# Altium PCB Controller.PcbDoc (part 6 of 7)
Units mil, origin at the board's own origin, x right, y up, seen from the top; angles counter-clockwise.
Board outline 9000 x 8000 mil, 6 copper layers (Top Layer, Layer 1, Layer 2, Layer 3, Layer 4, Bottom Layer), stack 61.699 mil thick; 761 components, 454 nets, 2369 pads, 1133 vias.
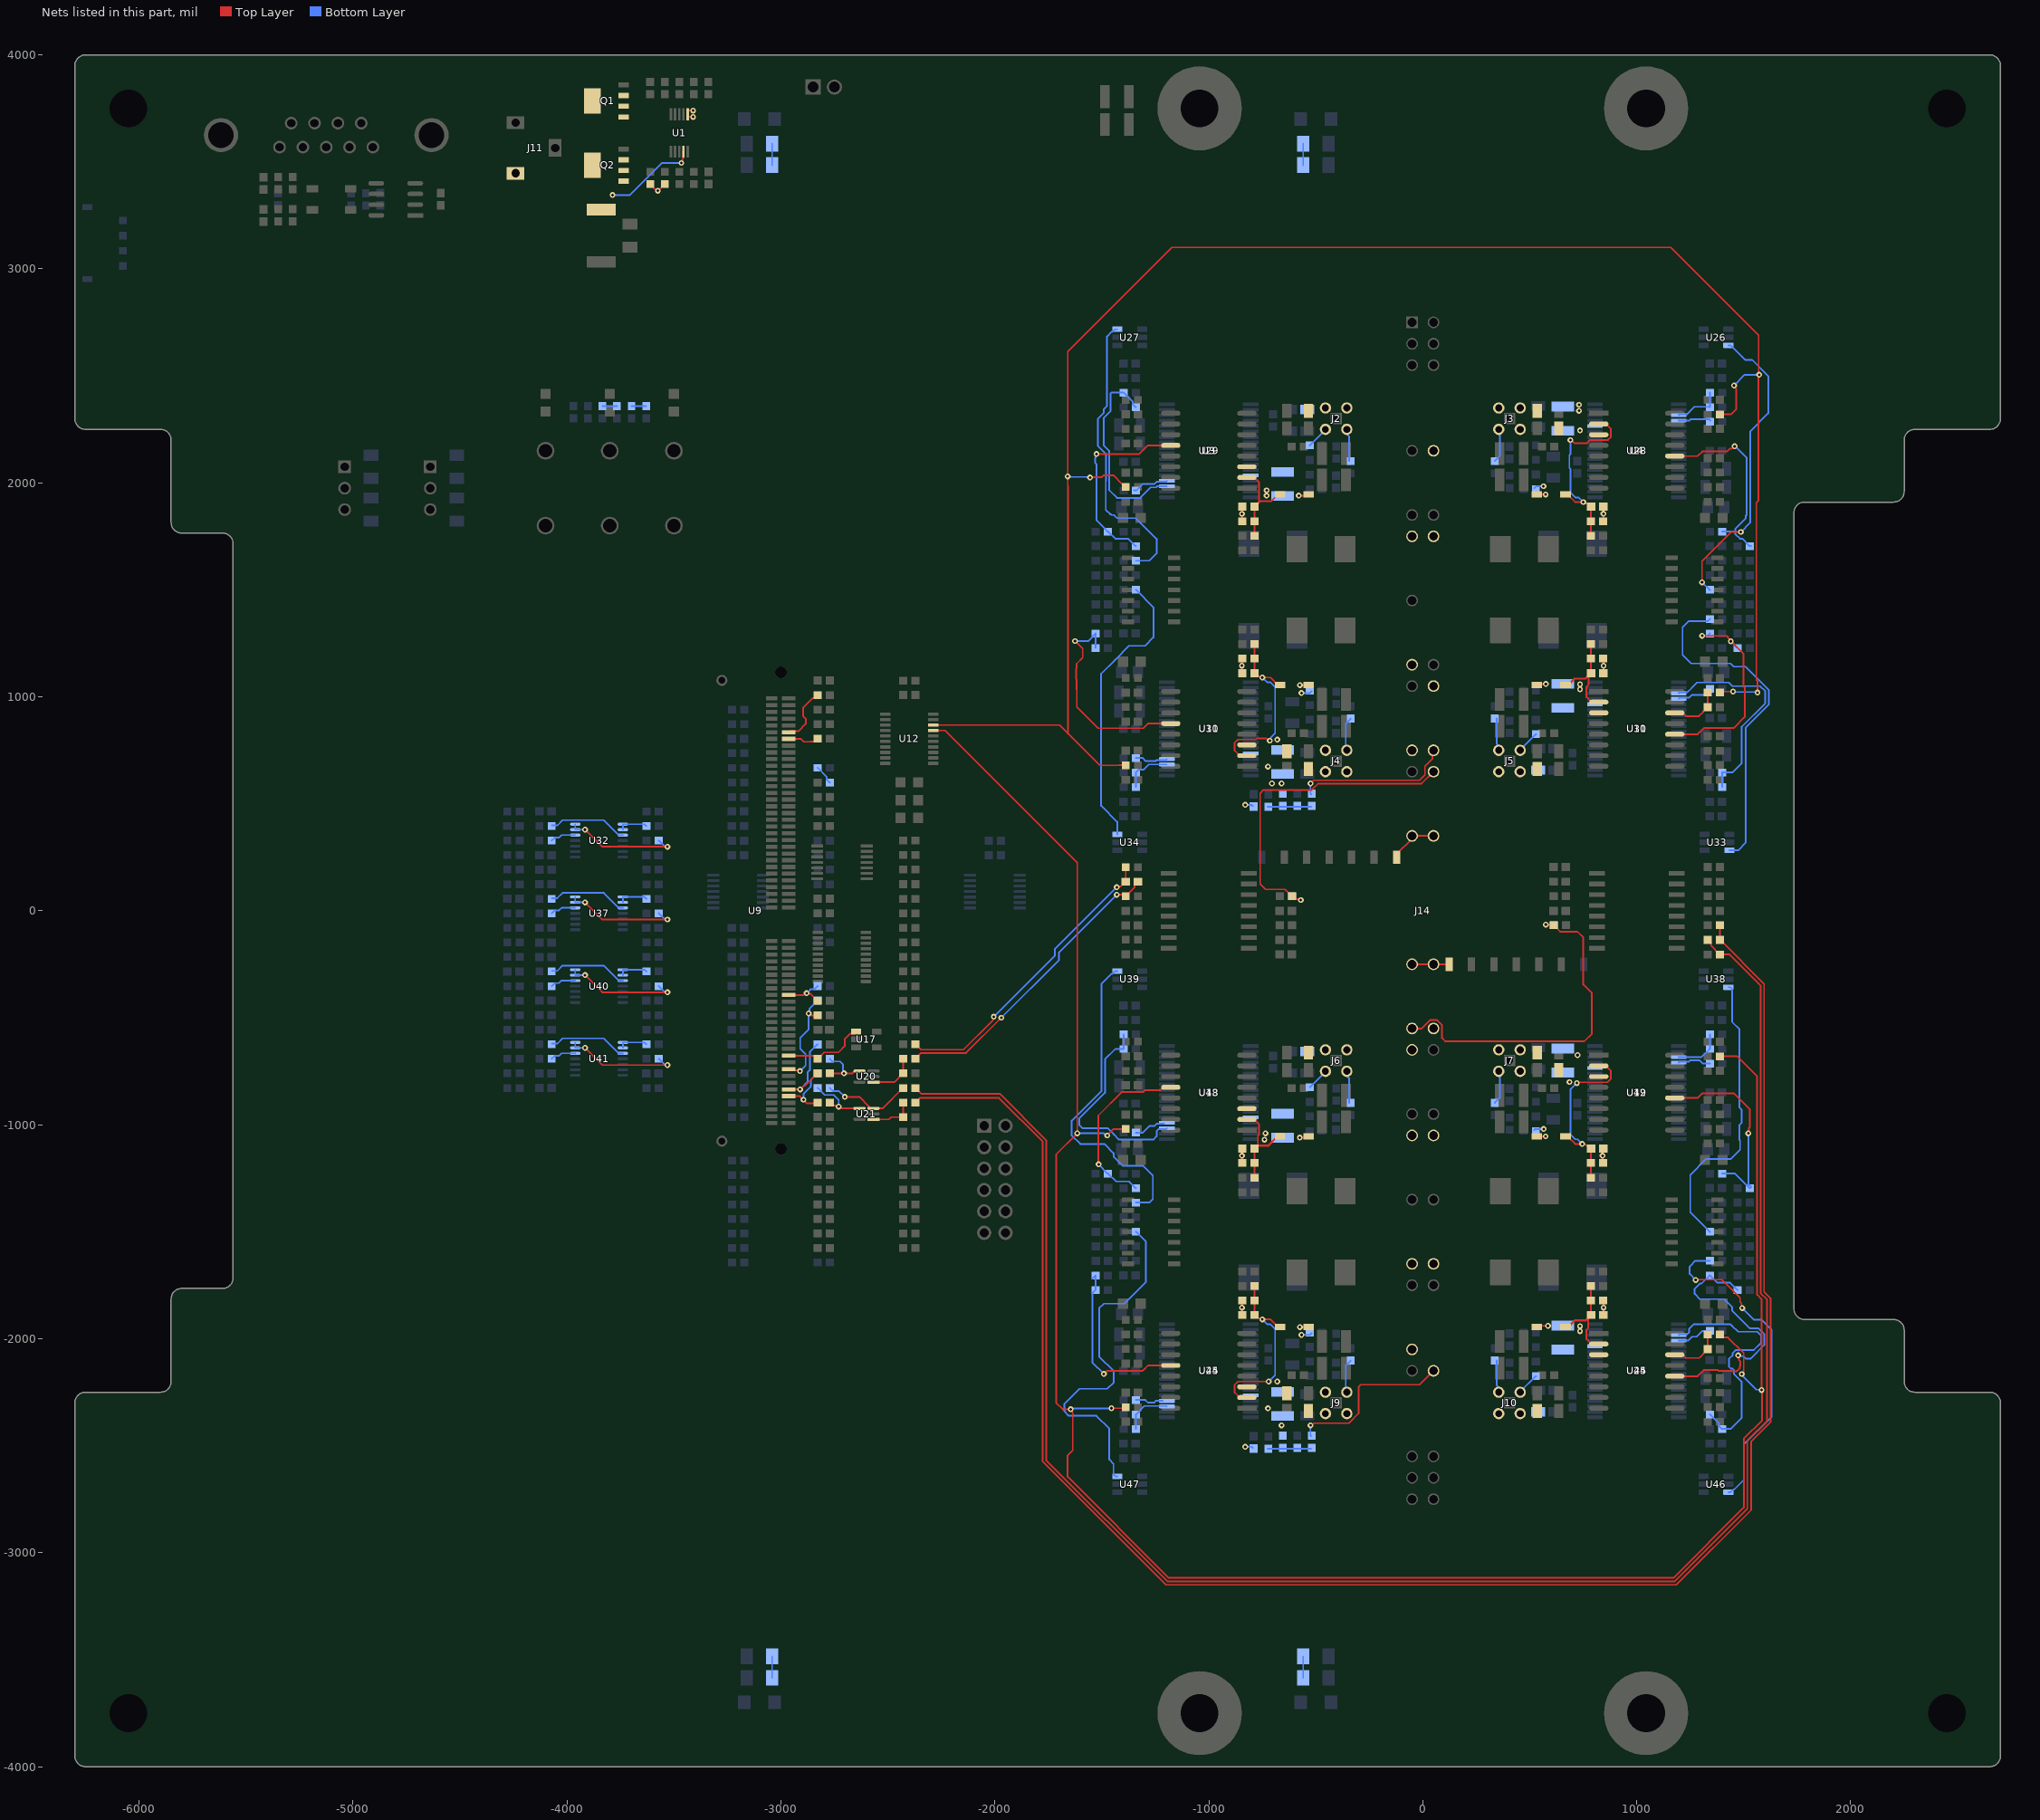
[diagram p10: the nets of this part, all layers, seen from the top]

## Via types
v1: diameter 27, hole 13, Top Layer to Bottom Layer, tented both sides, 1133 vias

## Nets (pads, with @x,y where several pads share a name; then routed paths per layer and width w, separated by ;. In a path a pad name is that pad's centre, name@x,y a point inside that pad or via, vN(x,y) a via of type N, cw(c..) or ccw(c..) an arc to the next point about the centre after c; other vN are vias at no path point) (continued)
NetR98_1: R98.1 R101.2 U20.1 | length 223.9
  Top Layer w8: U20.1@-2567.71,-800.59 -2470.12,-800.59 -2429.53,-760 R101.2@-2428.62,-760 R98.1@-2428.62,-692
NetR100_1: R100.1 R298.1 U20.4 | length 259.3
  Top Layer w8: R100.1@-2771.38,-760 v1(-2705,-760) -2666.14,-760 -2655.55,-749.41 U20.4@-2632.29,-749.41
  Bottom Layer w8: R298.1@-2771.38,-692 -2759.02,-704.36 -2724.24,-704.36 -2709.3,-719.3 -2709.3,-750.56 -2705,-754.86 v1(-2705,-760)
NetR102_1: R102.1 R308.2 U21.3 | length 427.1
  Top Layer w8: v1(-2701.19,-870) -2632.69,-870 -2589.93,-912.77 -2589.93,-920.27 -2586.79,-923.41 U21.3@-2567.71,-923.41 -2524.94,-923.41 -2429.53,-828 R102.1@-2428.62,-828
  Bottom Layer w8: R308.2@-2770.47,-828 R308.2@-2771.38,-828 -2757.42,-841.96 -2729.23,-841.96 v1(-2701.19,-870)
NetR107_1: R107.1 R308.1 U21.4 | length 296.4
  Top Layer w8: R107.1@-2771.38,-896 -2757.42,-909.96 v1@-2740.19,-909.96 ; v1(-2730,-915) -2724.86,-915 -2716.45,-923.41 U21.4@-2632.29,-923.41
  Bottom Layer w8: R308.1@-2828.62,-828 -2827.72,-828 -2794.76,-860.96 -2752.64,-860.96 -2730,-883.59 v1(-2730,-915) v1@-2733.64,-911.36
NetR108_1: R108.1 R112.2 U21.1 | length 212.1
  Top Layer w8: U21.1@-2568.14,-975 -2494.48,-975 -2484.07,-964.59 -2429.21,-964.59 R112.2@-2428.62,-964 R108.1@-2428.62,-896
NetR156_1: R156.1 R158.2 | length 100
  Bottom Layer w8: R158.2@-559.1,3485 R156.1@-559.1,3585
NetR157_1: R157.1 R159.2 | length 100
  Bottom Layer w8: R159.2@-3040.9,3485 R157.1@-3040.9,3585
NetR167_2: R167.2 R168.1 | length 68
  Bottom Layer w8: R168.1@-3698,2358.62 R167.2@-3630,2358.62
NetR169_1: R169.1 R170.2 | length 68
  Bottom Layer w8: R170.2@-3834,2358.62 R169.1@-3766,2358.62
NetR173_1: R173.1 U28.4 | length 155
  Bottom Layer w8: U28.4@1195.87,2290.75 1245.75,2290.75 1252.4,2297.4 1337.6,2297.4 R173.1@1345,2290
NetR185_1: R185.1 U29.4 | length 172.5
  Bottom Layer w8: R185.1@-1350,1965 -1338.47,1965 -1308.47,1995 -1253.96,1995 -1244.28,2004.67 -1200.44,2004.67 U29.4@-1195.87,2009.25
NetR211_1: R211.1 U30.4 | length 160.4
  Bottom Layer w8: U30.4@1195.87,990.75 1200.6,995.48 1244.28,995.48 1258.06,1009.26 1312.74,1009.26 1333.47,1030 R211.1@1340,1030
NetR228_1: R228.1 U31.4 | length 155.4
  Bottom Layer w8: R228.1@-1341.38,714 -1309,714 -1294.66,699.66 -1249.3,699.66 -1244.28,704.67 -1200.44,704.67 U31.4@-1195.87,709.25
NetR229_2: R229.2 R233.1 | length 92.8
  Bottom Layer w8: R229.2@-2828.62,668 -2827.72,668 -2786.24,626.52 -2786.24,613.96 -2772.28,600 R233.1@-2771.38,600
NetR244_1: R244.1 U32.8 U32.9 | length 139.4
  Bottom Layer w8: U32.9@-3738.78,379.18 U32.8@-3738.78,404.77 -3637.39,404.77 R244.1@-3628.62,396
NetR245_2: R245.2 U32.10 | length 371.8
  Bottom Layer w8: R245.2@-4071.38,399 -4045,399 -4020.34,423.66 -3827.69,423.66 -3757.62,353.59 U32.10@-3738.78,353.59
NetR246_1: R246.1 U32.6 U32.7 | length 543.4
  Top Layer w8: v1(-3915.18,379.18) -3835,299 v1(-3530,299)
  Bottom Layer w8: U32.7@-3961.22,404.77 U32.6@-3961.22,379.18 v1(-3915.18,379.18) ; R246.1@-3571.38,328 -3570.47,328 -3545.11,302.64 -3533.64,302.64 v1(-3530,299)
NetR247_2: R247.2 U32.5 | length 121.1
  Bottom Layer w8: R247.2@-4071.38,328 -4057.42,341.96 -4037.04,341.96 -4025,354 -3961.63,354 U32.5@-3961.22,353.59
NetR262_1: R262.1 U37.8 U37.9 | length 139.4
  Bottom Layer w8: U37.9@-3738.78,39.18 U37.8@-3738.78,64.77 -3637.39,64.77 R262.1@-3628.62,56
NetR263_2: R263.2 U37.10 | length 371.8
  Bottom Layer w8: R263.2@-4071.38,59 -4045,59 -4020.34,83.66 -3827.69,83.66 -3757.62,13.59 U37.10@-3738.78,13.59
NetR264_1: R264.1 U37.6 U37.7 | length 543.4
  Top Layer w8: v1(-3915.18,39.18) -3835,-41 v1(-3530,-41)
  Bottom Layer w8: U37.7@-3961.22,64.77 U37.6@-3961.22,39.18 v1(-3915.18,39.18) ; R264.1@-3571.38,-12 -3570.47,-12 -3545.11,-37.36 -3533.64,-37.36 v1(-3530,-41)
NetR265_2: R265.2 U37.5 | length 121.1
  Bottom Layer w8: R265.2@-4071.38,-12 -4057.42,1.96 -4037.04,1.96 -4025,14 -3961.63,14 U37.5@-3961.22,13.59
NetR277_1: R277.1 U40.8 U40.9 | length 139.4
  Bottom Layer w8: U40.9@-3738.78,-300.82 U40.8@-3738.78,-275.23 -3637.39,-275.23 R277.1@-3628.62,-284
NetR278_2: R278.2 U40.10 | length 371.8
  Bottom Layer w8: R278.2@-4071.38,-281 -4045,-281 -4020.34,-256.34 -3827.69,-256.34 -3757.62,-326.41 U40.10@-3738.78,-326.41
NetR279_1: R279.1 U40.6 U40.7 | length 543.4
  Top Layer w8: v1(-3915.18,-300.82) -3835,-381 v1(-3530,-381)
  Bottom Layer w8: U40.7@-3961.22,-275.23 U40.6@-3961.22,-300.82 v1(-3915.18,-300.82) ; R279.1@-3571.38,-352 -3570.47,-352 -3545.11,-377.36 -3533.64,-377.36 v1(-3530,-381)
NetR280_2: R280.2 U40.5 | length 121.1
  Bottom Layer w8: R280.2@-4071.38,-352 -4057.42,-338.04 -4037.04,-338.04 -4025,-326 -3961.63,-326 U40.5@-3961.22,-326.41
NetR293_1: R293.1 U41.8 U41.9 | length 139.4
  Bottom Layer w8: U41.9@-3738.78,-640.82 U41.8@-3738.78,-615.23 -3637.39,-615.23 R293.1@-3628.62,-624
NetR294_2: R294.2 U41.10 | length 371.8
  Bottom Layer w8: R294.2@-4071.38,-621 -4045,-621 -4020.34,-596.34 -3827.69,-596.34 -3757.62,-666.41 U41.10@-3738.78,-666.41
NetR300_1: R300.1 U41.6 U41.7 | length 543.4
  Top Layer w8: v1(-3915.18,-640.82) -3835,-721 v1(-3530,-721)
  Bottom Layer w8: U41.7@-3961.22,-615.23 U41.6@-3961.22,-640.82 v1(-3915.18,-640.82) ; R300.1@-3571.38,-692 -3570.47,-692 -3545.11,-717.36 -3533.64,-717.36 v1(-3530,-721)
NetR301_2: R301.2 U41.5 | length 121.1
  Bottom Layer w8: R301.2@-4071.38,-692 -4057.42,-678.04 -4037.04,-678.04 -4025,-666 -3961.63,-666 U41.5@-3961.22,-666.41
NetR303_1: R303.1 U42.4 | length 155.4
  Bottom Layer w8: U42.4@1195.87,-709.25 1200.44,-704.67 1244.28,-704.67 1249.3,-699.66 1294.66,-699.66 1309,-714 R303.1@1341.38,-714
NetR323_1: R323.1 U43.4 | length 148.8
  Bottom Layer w8: R323.1@-1341.38,-1037 -1307.85,-1037 -1275.85,-1005 -1253.8,-1005 -1244.28,-995.48 -1210.48,-995.48 U43.4@-1210,-995
NetR361_1: R361.1 U44.4 | length 162.5
  Bottom Layer w8: U44.4@1195.87,-2009.25 1239.69,-2009.25 1258.44,-1990.5 1280.35,-1990.5 1305.85,-1965 R361.1@1340,-1965
NetR373_1: R373.1 U45.4 | length 135.1
  Bottom Layer w8: R373.1@-1341.38,-2286 -1296.73,-2286 -1284.23,-2298.5 -1254.44,-2298.5 -1245.94,-2290 U45.4@-1215,-2290
NetR382_2: R382.2 R384.1 | length 100
  Bottom Layer w8: R384.1@-559.1,-3585 R382.2@-559.1,-3485
NetR383_2: R383.2 R385.1 | length 100
  Bottom Layer w8: R385.1@-3040.9,-3585 R383.2@-3040.9,-3485
NTC_P: J14.042 R237.1 | length 736.2
  Top Layer w8: v1(-525,595) -510,610 -15,610 10,635 10,675 45.64,710.64 45.64,745.64 J14.042@50,750
  Bottom Layer w8: v1(-525,595) -525,547.62 R237.1@-521,543.62
NTC_P_BIAS: R237.2 R238.1 R239.2 R240.2 | length 204
  Bottom Layer w8: R240.2@-725,486.38 -657,486.38 -589,486.38 R237.2@-521,486.38
NTC_S: J14.100 R378.1 | length 806.5
  Top Layer w8: v1(-525,-2405) -520.81,-2405 -510.81,-2395 -345.73,-2395 -300,-2349.27 -300,-2225 -290,-2215 -15,-2215 J14.100@50,-2150
  Bottom Layer w8: v1(-525,-2405) -525,-2452.38 R378.1@-521,-2456.38
NTC_S_BIAS: R378.2 R379.1 R380.2 R381.2 | length 204
  Bottom Layer w8: R381.2@-725,-2513.62 -657,-2513.62 -589,-2513.62 R378.2@-521,-2513.62
OC_1P: C22.1 D15.1 R37.1 R39.2 U11.2 | length 465
  Top Layer w8: D15.1@656.93,1055 D15.1@686.5,1055 ; C22.1@775,1099.58 775,1056.56 764.89,1046.46 764.89,998.46 788.35,975 U11.2@822.22,975 ; C22.1@786.42,1111 C22.1@786.42,1111 R39.2@786.38,1179 R37.1@786.38,1247
  Top Layer w10: D15.1@686.5,1055 686.5,1061.81 709.69,1085 760.42,1085 782.71,1107.29 C22.1@786.42,1111
OC_1S: C74.1 D30.1 R141.1 R143.2 U25.2 | length 463.7
  Top Layer w8: D30.1@656.93,-1945 D30.1@686.5,-1945 ; C74.1@772.97,-1901.5 772.97,-1950.49 764.89,-1958.57 764.89,-2001.54 788.35,-2025 U25.2@822.22,-2025 ; C74.1@786.42,-1889 C74.1@786.42,-1889 R143.2@786.38,-1821 R141.1@786.38,-1753
  Top Layer w10: D30.1@686.5,-1945 686.5,-1938.2 709.69,-1915 760.42,-1915 771.61,-1903.81 771.61,-1902.86 772.5,-1901.98 773.45,-1901.98 C74.1@786.42,-1889
OC_2P: C21.1 D14.1 R36.1 R38.2 U10.2 | length 871
  Top Layer w8: U10.2@-822.22,725 -856.1,725 -879.56,748.46 -879.56,784.72 -864.27,800 -780.18,800 -774.68,805.5 -730.52,805.5 -720.14,795.12 v1(-715,795.12) ; C21.1@-790,1115 -786.38,1118.62 R38.2@-786.38,1179 ; C21.1@-786.42,1111 -771.56,1096.14 -763.78,1096.14 ; R36.1@-786.38,1247 -786.38,1186.38 R38.2@-785,1185 ; v1(-750,1090) -711.77,1090 -676.77,1055 D14.1@-670,1055
  Bottom Layer w8: v1(-750,1090) -728.18,1068.18 -713.18,1068.18 -690,1045 -690,830 -711.36,808.64 -711.36,798.75 v1(-715,795.12)
OC_2S: C73.1 D29.1 R140.1 R142.2 U24.2 | length 872.9
  Top Layer w8: U24.2@-822.22,-2275 -856.1,-2275 -879.56,-2251.54 -879.56,-2215.28 -864.27,-2200 v1(-720,-2200) ; C73.1@-790,-1885 -786.38,-1881.38 R142.2@-786.38,-1821 ; C73.1@-786.42,-1889 -771.56,-1903.86 -763.78,-1903.86 -761.28,-1906.36 -753.64,-1906.36 v1(-750,-1910) -711.77,-1910 -676.77,-1945 D29.1@-670,-1945 ; R140.1@-786.38,-1753 -786.38,-1813.62 R142.2@-785,-1815
  Bottom Layer w8: v1(-750,-1910) -728.18,-1931.82 -713.18,-1931.82 -690,-1955 -690,-2170 v1(-720,-2200)
OC_3P: C19.1 D4.1 R28.2 R30.1 U3.2 | length 444.8
  Top Layer w8: U3.2@-822.22,2025 -788.35,2025 -765,2001.65 -765,1991.54 -764.89,1991.43 -764.89,1958.57 -765,1958.46 -765,1910.42 -760.92,1914.5 -707.27,1914.5 -681.77,1940 D4.1@-660,1940 ; R30.1@-786.38,1753 R28.2@-786.38,1821 C19.1@-786.42,1889 C19.1@-786.42,1889 ; D4.1@-660,1945 D4.1@-656.93,1945
  Top Layer w10: C19.1@-786.42,1889 -765,1910.42
OC_3S: C70.1 D19.1 R121.2 R125.1 U18.2 | length 463.1
  Top Layer w8: U18.2@-822.22,-975 -788.35,-975 -764.89,-998.46 -764.89,-1046.46 -770.61,-1052.17 -770.61,-1096.14 -772.97,-1098.5 -785.47,-1111 C70.1@-786.42,-1111 C70.1@-786.42,-1111 R121.2@-786.38,-1179 R125.1@-786.38,-1247 ; D19.1@-686.5,-1055 D19.1@-656.93,-1055
  Top Layer w10: C70.1@-772.97,-1098.5 -723.19,-1098.5 -686.5,-1061.8 D19.1@-686.5,-1055
OC_4P: C20.1 D5.1 R29.2 R31.1 U4.2 | length 907.8
  Top Layer w8: D5.1@670,1945 676.77,1945 711.77,1910 v1(750,1910) 753.64,1906.36 761.28,1906.36 763.78,1903.86 771.56,1903.86 C20.1@786.42,1889 ; v1(690,2199.76) 695.14,2199.76 710.4,2184.5 764.68,2184.5 780.18,2200 865.31,2200 879.56,2214.24 879.56,2251.54 856.1,2275 U4.2@822.22,2275 ; R29.2@785,1815 786.38,1813.62 R31.1@786.38,1753 ; R29.2@786.38,1821 786.38,1881.38 C20.1@790,1885
  Bottom Layer w8: v1(690,2199.76) 690,2134.77 685,2129.77 685,2069.93 690,2064.93 690,1955 713.18,1931.82 728.18,1931.82 v1(750,1910)
OC_4S: C71.1 D20.1 R122.2 R126.1 U19.2 | length 898.9
  Top Layer w8: D20.1@670,-1055 676.77,-1055 711.77,-1090 v1(745,-1090) 748.64,-1093.64 761.28,-1093.64 763.78,-1096.14 771.56,-1096.14 C71.1@786.42,-1111 ; v1(720,-805) 723.46,-801.54 862.73,-801.54 879.56,-784.72 879.56,-748.46 856.1,-725 U19.2@822.22,-725 U19.2@788.35,-725 ; R122.2@785,-1185 786.38,-1186.38 R126.1@786.38,-1247 ; R122.2@786.38,-1179 786.38,-1118.62 C71.1@790,-1115
  Bottom Layer w8: v1(720,-805) 720,-805.66 690,-835.66 690,-1045 713.18,-1068.18 723.18,-1068.18 v1(745,-1090)
P+: J14.049 J14.050 R66.2 | length 230.2
  Top Layer w8: R66.2@-122.83,250 -122.83,264.76 -50,337.6 J14.049@-50,350 J14.050@50,350
P-: J14.044 R71.1 R260.1 | length 1535.1
  Top Layer w8: v1@-578.99,54.04 -597.42,54.04 R71.1@-611.38,68 -612.28,68 -644.28,100 -735,100 -760,125 -760,549 -744.53,564.47 -519.47,564.47 -490,593.94 -6.06,593.94 J14.044@50,650
  Bottom Layer w8: R260.1@-611.38,68 -597.42,54.04 -578.99,54.04 -575.05,50.11 v1(-569.91,50.11)
P\G\_\1\P\: R231.2 R235.2 U30.3 | length 1003.2
  Bottom Layer w8: U30.3@1195.87,1016.34 1200.6,1021.07 1236.11,1021.07 1257.52,1042.48 1257.52,1043.59 1280.89,1066.96 1429.4,1066.96 1446.36,1050 1576.56,1050 1600.5,1026.06 1600.5,970.5 1490.5,860.5 1490.5,689.44 1447.06,646 R231.2@1398.62,646 R235.2@1398.62,578
P\G\_\1\S\: R374.2 R376.2 U44.3 | length 1167.5
  Bottom Layer w8: U44.3@1195.87,-1983.66 1200.6,-1978.93 1236.11,-1978.93 1244.28,-1970.76 1244.28,-1954.44 1265.68,-1933.04 1438.04,-1933.04 1444.5,-1939.5 1445.56,-1939.5 1473.66,-1967.59 1562.6,-1967.59 1568.91,-1973.91 1580,-1984.99 1580,-2020 1547.38,-2052.62 1463.5,-2052.62 1448.56,-2067.55 1448.56,-2076.44 1430.39,-2094.61 1430.39,-2130.31 1439.43,-2139.36 1446.98,-2139.36 1454.01,-2146.39 1454.01,-2164.96 1490.5,-2201.45 1490.5,-2369.5 1438,-2422 R376.2@1398.62,-2422 1397.72,-2422 1383.76,-2408.04 1383.76,-2395.48 1342.28,-2354 R374.2@1341.38,-2354
P\G\_\2\P\: R232.2 R236.2 U31.3 | length 229.1
  Bottom Layer w8: R236.2@-1341.38,578 R232.2@-1341.38,646 -1327.42,659.96 -1303.71,659.96 -1280,683.66 U31.3@-1195.87,683.66
P\G\_\2\S\: R375.2 R377.2 U45.3 | length 230.6
  Bottom Layer w8: R377.2@-1341.38,-2422 R375.2@-1341.38,-2354 -1340.47,-2354 -1300.97,-2314.5 -1197.7,-2314.5 U45.3@-1195.87,-2316.34
P\G\_\3\P\: R163.2 R165.2 U29.3 | length 938.5
  Bottom Layer w8: R165.2@-1341.38,2354 -1342.28,2354 -1356.24,2367.96 -1356.24,2380.52 -1397.72,2422 -1455.31,2422 -1460,2417.31 -1460,2335 -1475.53,2319.47 -1475.53,2319.21 -1490.5,2304.25 -1490.5,2174.44 -1465,2148.94 -1465,1965 -1429.53,1929.53 -1320.47,1929.53 -1310,1940 -1310,1941.06 -1272.06,1979 -1247.33,1979 -1242.67,1983.66 U29.3@-1195.87,1983.66
P\G\_\3\S\: R292.2 R297.2 U43.3 | length 1007
  Bottom Layer w8: R292.2@-1398.62,-578 R297.2@-1398.62,-646 -1437.06,-646 -1485.5,-694.44 -1485.5,-850.5 -1606,-971 -1606,-1000.56 -1591.06,-1015.5 -1473.44,-1015.5 -1444.31,-1044.62 -1444.31,-1045.09 -1419.41,-1070 -1260,-1070 -1244.28,-1054.28 -1244.28,-1029.24 -1236.11,-1021.07 -1200.6,-1021.07 U43.3@-1195.87,-1016.34
P\G\_\4\P\: R162.2 R164.2 U28.3 | length 231.2
  Bottom Layer w8: U28.3@1195.87,2316.34 1200.6,2321.07 1236.11,2321.07 1244.28,2329.24 1244.28,2330.61 1269.18,2355.5 1339.88,2355.5 R164.2@1341.38,2354 R162.2@1341.38,2422
P\G\_\4\S\: R291.2 R295.2 U42.3 | length 229.1
  Bottom Layer w8: U42.3@1195.87,-683.66 1302.81,-683.66 1340.47,-646 R295.2@1341.38,-646 R291.2@1341.38,-578
PG_1P: R201.2 U33.6 | length 1592.8
  Bottom Layer w8: R201.2@1341.38,1364 1330.64,1353.26 1241.7,1353.26 1214,1325.56 1214,1196 1254.22,1155.78 1438.2,1155.78 1453.05,1140.94 1508.25,1140.94 1616.5,1032.69 1616.5,963.87 1510,857.37 1510,319.07 1473.53,282.6 U33.6@1433.07,282.6
PG_1S: R349.2 U46.6 | length 1506.2
  Top Layer w8: v1(1275.5,-1726) 1277.5,-1724 1399,-1724 1483,-1808 1483,-1827.45 1489.4,-1833.85 1489.4,-1853.33 v1(1493.03,-1856.97)
  Bottom Layer w8: v1(1275.5,-1726) 1275.5,-1725.79 1247.14,-1697.43 1247.14,-1662.86 1250,-1660 1250,-1659.68 1273.68,-1636 R349.2@1341.38,-1636 ; U46.6@1428.07,-2717.4 1438.9,-2717.4 1451.5,-2704.8 1455.54,-2704.8 1500,-2660.33 1500,-2495 1630,-2365 1630,-1959.87 1581.27,-1911.14 1547.2,-1911.14 v1(1493.03,-1856.97)
PG_2P: R198.2 U34.6 | length 1353.6
  Bottom Layer w8: U34.6@-1428.07,357.4 -1428.07,415.85 -1503.06,490.84 -1503.06,706.69 -1503,706.75 -1503,1108.06 -1437.95,1173.11 -1372.91,1238.16 -1298.16,1238.16 -1258.5,1277.81 -1258.5,1418.03 -1340.47,1500 R198.2@-1341.38,1500
PG_2S: R343.2 U47.6 | length 1693.7
  Bottom Layer w8: U47.6@-1428.07,-2642.6 -1436.98,-2642.6 -1445.77,-2633.8 -1445.77,-2584.23 -1465.5,-2564.5 -1465.5,-2460.53 -1465,-2460.03 -1465,-2420 -1525,-2360 -1655,-2360 -1675,-2340 -1675,-2303.94 -1605,-2233.94 -1475,-2233.94 -1444.47,-2203.41 -1444.47,-2151.84 -1512.62,-2083.69 -1512.62,-1857.62 -1491,-1836 -1395.15,-1836 -1293.61,-1734.46 -1293.61,-1546.86 -1340.47,-1500 R343.2@-1341.38,-1500
PG_3P: R194.2 U27.6 | length 1378.7
  Bottom Layer w8: U27.6@-1428.07,2717.4 -1438.9,2717.4 -1451.5,2704.8 -1455.54,2704.8 -1476,2684.33 -1476,2359 -1491.53,2343.47 -1491.53,2325.84 -1518.69,2298.69 -1518.69,2172.69 -1481,2135 -1481,2008.3 -1481.47,2007.83 -1481.47,1873.42 -1461,1852.96 -1457.58,1852.96 -1454.13,1849.5 -1443.48,1849.5 -1428.98,1835 -1341.33,1835 -1244.28,1737.95 -1244.28,1669.65 -1277.94,1636 R194.2@-1341.38,1636
PG_3S: R337.2 U39.6 | length 1526.1
  Bottom Layer w8: U39.6@-1428.07,-282.6 -1438.9,-282.6 -1451.5,-295.2 -1455.54,-295.2 -1501.5,-341.17 -1501.5,-841.5 -1640.5,-980.5 -1640.5,-1050.56 -1601.06,-1090 -1488.67,-1090 -1445.23,-1133.44 -1445.23,-1148.75 -1402.39,-1191.6 -1307.34,-1191.6 -1261.64,-1237.3 -1261.64,-1346.64 -1279,-1364 R337.2@-1341.38,-1364
PG_4P: R197.2 U26.6 | length 1414.6
  Top Layer w8: v1(1305,1535) 1305,1634.47 1440.53,1770 v1@1485,1770
  Bottom Layer w8: v1(1305,1535) 1305.47,1535 1340.47,1500 R197.2@1341.38,1500 ; U26.6@1428.07,2642.6 1438.9,2642.6 1506.81,2574.68 1538.88,2574.68 1615,2498.56 1615,2325 1530,2240 1530,1813.66 v1(1486.57,1770.23)
PG_4S: R342.2 U38.6 | length 1381.5
  Bottom Layer w8: R342.2@1341.38,-1500 1340.47,-1500 1250,-1409.53 1250,-1235 1325,-1160 1440,-1160 1483,-1117 1483,-1073.51 1480,-1070.51 1480,-1000.52 1490.5,-990.02 1490.5,-930.27 1480,-919.77 1480,-553.72 1445.77,-519.49 1445.77,-366.2 1436.98,-357.4 U38.6@1428.07,-357.4
RDY_1P: R203.2 R205.1 U11.12 | length 976.7
  Top Layer w8: U11.12@1177.78,825 1284.78,825 1314.78,855 1455,855 1505,905 1505,1042.53 1499,1048.53 1499,1199.89 1440,1258.89 v1@1440,1260 ; v1(1305.5,1285) 1421.06,1285 1426.72,1279.34 1426.72,1277.31 1439.55,1264.48 v1(1439.55,1259.34)
  Bottom Layer w8: v1(1305.5,1285) 1330.38,1285 R203.2@1341.38,1296 ; v1(1439.55,1259.34) 1439.55,1258.92 1470.47,1228 R205.1@1471.38,1228
RDY_1S: R353.2 R355.1 U25.12 | length 1286
  Top Layer w8: U25.12@1177.78,-2175 1284.78,-2175 1312.96,-2146.82 1379.02,-2146.82 1383.05,-2150.85 1444.05,-2150.85 1445.33,-2152.12 1466.45,-2152.12 1467.73,-2150.85 1468.98,-2150.85 1481.6,-2138.23 1481.6,-2128.93 1483.57,-2126.96 1483.57,-2105.83 1477.7,-2099.96 1477.7,-2081.75 v1(1474.06,-2078.12)
  Bottom Layer w8: R355.1@1471.38,-1772 1470.47,-1772 1436.47,-1738 1376.28,-1738 1342.28,-1704 1340.47,-1704 1301.95,-1742.52 1295.04,-1742.52 1270.47,-1767.09 1270.47,-1790.47 1295,-1815 1408.98,-1815 1445.23,-1851.25 1445.23,-1867.86 1528.97,-1951.59 1569.23,-1951.59 1596,-1978.37 1596,-2029 1531.06,-2093.94 1510.6,-2093.94 1498.42,-2081.75 1477.7,-2081.75 v1(1474.06,-2078.12)
RDY_2P: R204.2 R207.1 U10.12 | length 1007
  Top Layer w8: v1(-1625.49,1260.57) -1589.5,1224.59 -1589.5,1183.13 -1618,1154.63 -1618,1133.32 -1620.53,1130.79 -1620.53,1083.15 -1618,1080.62 -1618,1032.81 -1617,1031.81 -1617,952 -1518.14,853.14 -1306.64,853.14 -1284.78,875 U10.12@-1177.78,875
  Bottom Layer w8: v1(-1625.49,1260.57) -1624.91,1260 -1564.62,1260 -1543.48,1281.14 -1543.48,1282.04 -1529.53,1296 -1528.62,1295.09 R207.1@-1528.62,1228
RDY_2S: R354.2 R357.1 U24.12 | length 840
  Top Layer w8: v1(-1490.3,-2164.7) -1489.7,-2164.7 -1475.61,-2150.61 -1310.9,-2150.61 -1307.15,-2146.86 -1306.64,-2146.86 -1284.78,-2125 U24.12@-1177.78,-2125
  Bottom Layer w8: R354.2@-1543.48,-1717.96 -1529.53,-1704 R354.2@-1528.62,-1704 R357.1@-1528.62,-1772 -1529.53,-1772 -1543.48,-1785.96 -1543.48,-1786.86 -1544.62,-1788 -1544.62,-2110.38 v1(-1490.3,-2164.7)
RDY_3P: R190.1 R192.2 U3.12 | length 913.5
  Top Layer w8: v1(-1525,2135) -1324.78,2135 -1284.78,2175 U3.12@-1177.78,2175
  Bottom Layer w8: v1(-1525,2135) -1528.64,2131.36 -1528.64,2118.93 -1532,2115.56 -1532,2094.44 -1525,2087.44 -1525,1825.62 -1486.24,1786.86 -1486.24,1785.96 -1472.28,1772 -1470.47,1772 -1437.17,1738.7 -1376.98,1738.7 -1342.28,1704 R192.2@-1341.38,1704
RDY_3S: R329.1 R333.2 U18.12 | length 841.8
  Top Layer w8: v1(-1515,-1185) -1516.5,-1183.5 -1516.5,-957.02 -1406.34,-846.86 -1306.64,-846.86 -1298.28,-838.5 -1225.15,-838.5 -1211.65,-825 U18.12@-1177.78,-825
  Bottom Layer w8: v1(-1515,-1185) -1515,-1185.28 -1472.28,-1228 -1470.47,-1228 -1433.47,-1265 -1373.28,-1265 -1342.28,-1296 R333.2@-1341.38,-1296
RDY_4P: R188.1 R191.2 U4.12 | length 912.5
  Top Layer w8: U4.12@1177.78,2125 1284.78,2125 1306.64,2146.86 1421.72,2146.86 1434,2159.14 1442.69,2159.14 1454.36,2170.81 v1(1457.5,2170.81)
  Bottom Layer w8: R188.1@1398.62,1772 1459.07,1772 1461.07,1770 ; v1(1457.5,2170.81) 1459.5,2170.81 1513.76,2116.55 1513.76,1850.07 1510,1846.31 1510,1835 1461.07,1786.07 1461.07,1770 ; R191.2@1528.62,1704 1527.72,1704 1492.91,1738.81 1481.92,1738.81 1461.07,1759.66 1461.07,1770 ; R191.2@1533.62,1705 1534.62,1706 R191.2@1534.62,1704.91
RDY_4S: R327.1 R332.2 U19.12 | length 931.6
  Top Layer w8: U19.12@1177.78,-875 1284.78,-875 1306.64,-853.14 1453.7,-853.14 1528.5,-927.94 1528.5,-1010.5 1524.5,-1014.5 1524.5,-1037 v1(1521.5,-1040)
  Bottom Layer w8: R327.1@1398.62,-1228 1459.72,-1228 1527.72,-1296 R332.2@1528.62,-1296 1535,-1289.62 1528.5,-1283.12 1522.58,-1283.12 1521.5,-1282.04 v1(1521.5,-1040)
RLIM_1P: R210.1 U30.32
RLIM_1S: R360.1 U44.32
RLIM_2P: R226.1 U31.32
RLIM_2S: R372.1 U45.32
RLIM_3P: R180.1 U29.32
RLIM_3S: R317.1 U43.32
RLIM_4P: R166.1 U28.32
RLIM_4S: R296.1 U42.32
RSTEN_12P_FILT: C27.1 R42.2 U11.14 | length 227.8
  Top Layer w8: U11.14@1196.73,925 1214.82,925 1229.82,910 1291.06,910 1310.5,929.44 1310.5,932.03 1330.47,952 C27.1@1331.42,952 C27.1@1331.42,952 R42.2@1331.38,1020
RSTEN_12S_FILT: C77.1 R145.2 U25.14 | length 228.4
  Top Layer w8: U25.14@1196.73,-2075 1214.82,-2075 1229.82,-2090 1292.01,-2090 1311.45,-2070.56 1311.45,-2067.97 1315.61,-2063.81 1315.61,-2062.86 1330.47,-2048 C77.1@1331.42,-2048 C77.1@1331.42,-2048 R145.2@1331.38,-1980
RSTEN_P: R45.1 U9.109 | length 266.8
  Top Layer w8: U9.109@-2963.58,834.65 -2959.36,838.87 -2919.1,838.87 -2884.15,873.83 -2884.15,896.98 -2895.24,908.08 -2895.24,949.58 -2850.78,994.04 -2842.58,994.04 R45.1@-2828.62,1008
RSTEN_P_BUF: R17.1 R26.1 R42.1 R55.1 U12.18 | length 8858.2
  Top Layer w8: U12.18@-2287.8,867.98 -1697.98,867.98 -1659.57,829.57 ; v1@-1659.75,2030.25 -1659.5,2030.5 -1659.5,2613.64 -1173.14,3100 1159.75,3100 1569.5,2690.25 v1@1569.5,2505 ; v1(-1659.5,2030) -1659.5,1986.06 -1659,1985.56 -1659,829 -1509.5,679.5 ; v1(-1555,2025) -1554,2026 -1501.4,2026 -1491.9,2035.5 -1446.56,2035.5 -1405.02,1993.96 -1402.58,1993.96 R26.1@-1388.62,1980 ; -1508.7,679.5 -1420.5,679.5 -1420,680 R55.1@-1388.62,680 ; R42.1@1388.62,1020 1393.62,1025 1394.12,1024.5 v1(1450,1024.5) ; R17.1@1388.62,2320 1440,2320 1465,2345 1465,2440.81 1455,2450.81 v1(1455,2455) ; v1(1564.5,1020) 1564.5,1072.87 1559,1078.37 1559,1907.43 1568.86,1917.29 1568.86,2501.36 v1(1572.5,2505)
  Bottom Layer w8: v1(-1659.5,2030) -1657,2027.5 -1557.5,2027.5 v1(-1555,2025) ; v1(1450,1024.5) 1452.25,1022.25 1562.25,1022.25 v1(1564.5,1020) ; v1(1455,2455) 1505,2505 v1(1572.5,2505)
RSTEN_S: R52.1 U9.107 | length 146.6
  Top Layer w8: U9.107@-2963.58,803.15 -2906.09,803.15 -2892.48,789.53 -2862.44,789.53 -2861.92,790.04 -2842.58,790.04 R52.1@-2828.62,804
RSTEN_S_BUF: R96.1 R113.1 R145.1 R154.1 U12.17 | length 10547
  Top Layer w8: U12.17@-2287.8,842.39 -2232.39,842.39 -1615,225 v1(-1615,-1040) -1714,-1139 -1714,-2299.56 -1683.56,-2330 v1(-1645.5,-2330) -1645.5,-2334.69 -1636,-2344.19 -1636,-2521 -1660,-2545 -1660,-2644.75 -1186.75,-3118 1171.75,-3118 1500.75,-2789 1500.75,-2466.37 1585.5,-2381.62 1585.5,-2242 v1(1583.5,-2240) ; v1(-1475,-1050) -1445,-1020 R113.1@-1388.62,-1020 ; v1(-1455,-2325) -1393.62,-2325 R154.1@-1388.62,-2320 ; R145.1@1388.62,-1980 1402.58,-1993.96 1425.97,-1993.96 1499.56,-2067.55 1499.56,-2099.2 1499.57,-2133.58 1499.56,-2151.18 1490.5,-2160.25 v1(1490.5,-2165.39) ; R96.1@1388.62,-680 1470,-680 1563,-773 1563,-1794.32 1583.11,-1814.43 v1@1583.11,-2237.25
  Bottom Layer w8: v1(-1645.5,-2330) -1641.86,-2326.36 -1456.36,-2326.36 v1(-1455,-2325) ; v1(-1615,-1040) -1490.14,-1040 -1480.14,-1050 v1(-1475,-1050) ; v1(1490.5,-2165.39) 1490.5,-2170.5 1558,-2238 1581.5,-2238 v1(1583.5,-2240)
S+: J14.061 J14.062 R84.2 | length 172.8
  Top Layer w8: J14.061@-50,-250 J14.062@50,-250 R84.2@122.83,-250
S-: J14.067 R77.1 R267.1 | length 1651.5
  Top Layer w8: J14.067@-50,-550 -5.67,-550 33.7,-510.64 66.3,-510.64 90,-534.33 90,-595 105,-610 755,-610 790,-575 790,-385 750,-345 750,-125 722.96,-97.96 642.24,-97.96 612.28,-68 R77.1@611.38,-68 608.38,-65 v1(575,-65)
  Bottom Layer w8: v1(575,-65) 608.38,-65 R267.1@611.38,-68
S_1P: C22.2 C36.1 C145.2 D15.2 J5.2 J5.3 J5.4 J5.5 J14.033 J14.036 R39.1 R210.2 R216.1 R223.2 U11.3 | length 382.8
  Top Layer w8: D15.2@525,1055 530,1060 v1(575,1060)
  Top Layer w10: C22.2@843.58,1111 845,1112.42 845,1177.62 R39.1@843.62,1179
  Bottom Layer w8: R216.1@345,898.38 345,782.11 360,767.11 J5.4@360,750 ; J5.2@455,750 455,752.28 527.72,825 R223.2@528.62,825 R223.2@529.53,825
  other v1: 735,1035 735,1058.5 845,1145
S_1S: C74.2 C85.1 C262.2 D30.2 J10.2 J10.3 J10.4 J10.5 J14.089 J14.090 R143.1 R360.2 R366.1 R370.2 U25.3 | length 392.8
  Top Layer w8: D30.2@525,-1945 530,-1940 v1(585,-1940)
  Top Layer w10: C74.2@843.58,-1889 845,-1887.58 845,-1822.38 R143.1@843.62,-1821
  Bottom Layer w8: R366.1@345,-2101.62 345,-2217.89 360,-2232.89 J10.4@360,-2250 ; J10.2@455,-2250 455,-2247.72 527.72,-2175 R370.2@528.62,-2175 R370.2@529.53,-2175
  other v1: 735,-1965 735,-1941.5 845,-1855
S_2P: C21.2 C32.1 C35.2 C150.2 D14.2 J4.2 J4.3 J4.4 J4.5 J14.041 R38.1 R213.2 R217.1 R226.2 R239.1 U10.3 | length 329.8
  Top Layer w8: v1(-845.75,1145.48) -845.75,1120.75 C21.2@-845,1120 ; v1@-845.75,1145.75 -845.75,1176.87 R38.1@-843.62,1179 ; v1(-574.25,1054.52) -546.61,1054.52 D14.2@-545,1052.91
  Bottom Layer w8: v1(-830,495) -800,495 C150.2@-795,490 ; v1(-567.1,1017.9) -527.1,1017.9 R213.2@-520,1025 ; J4.2@-360,755 -360,874.47 -337,897.47 R217.1@-337,898.38
  other v1: -705,595 -660,595 -723.42,674.02 -680,800
S_2S: C73.2 C81.1 C84.2 C266.2 D29.2 J9.2 J9.3 J9.4 J9.5 J14.097 R142.1 R363.2 R367.1 R372.2 R380.1 U24.3 | length 339.1
  Top Layer w8: C73.2@-843.58,-1889 -845,-1887.58 v1(-845,-1855) -845,-1822.38 R142.1@-843.62,-1821 ; v1(-574.25,-1945.48) -546.61,-1945.48 D29.2@-545,-1947.09
  Bottom Layer w8: v1(-830,-2505) -800,-2505 C266.2@-795,-2510 ; v1(-567.1,-1982.1) -527.1,-1982.1 R363.2@-520,-1975 ; J9.2@-360,-2245 -360,-2125.53 -337,-2102.53 R367.1@-337,-2101.62
  other v1: -660,-2405 -723.32,-2325.5 -680,-2200
S_3P: C8.1 C19.2 C94.2 D4.2 J2.2 J2.3 J2.4 J2.5 J14.021 J14.022 R28.1 R175.2 R179.1 R180.2 U3.3 | length 387.8
  Top Layer w8: v1(-580,1940) -530,1940 D4.2@-525,1945
  Top Layer w10: R28.1@-843.62,1821 -845,1822.38 -845,1887.58 C19.2@-843.58,1889
  Bottom Layer w8: R175.2@-529.53,2175 R175.2@-528.62,2175 -527.72,2175 -455,2247.72 J2.2@-455,2250 ; J2.4@-360,2250 -360,2232.89 -345,2217.89 R179.1@-345,2101.62
  other v1: -845,1855 -730,1940 -730,1965
S_3S: C57.1 C70.2 C205.2 D19.2 J6.2 J6.3 J6.4 J6.5 J14.077 J14.078 R121.1 R307.2 R316.1 R317.2 U18.3 | length 373
  Top Layer w8: v1(-575,-1060) D19.2@-532.69,-1060
  Top Layer w10: R121.1@-843.62,-1179 -845,-1177.62 -845,-1112.42 C70.2@-843.58,-1111
  Bottom Layer w8: R307.2@-529.53,-825 R307.2@-528.62,-825 -527.72,-825 -455,-752.28 J6.2@-455,-750 ; J6.4@-360,-750 -360,-767.11 -345,-782.11 R316.1@-345,-898.38
  other v1: -845,-1145 -740,-1070 -735,-1040
S_4P: C9.2 C12.1 C20.2 D5.2 J3.2 J3.3 J3.4 J3.5 J14.014 R29.1 R166.2 R178.1 R183.2 U4.3 | length 292.7
  Top Layer w8: D5.2@545,1947.09 546.61,1945.48 v1(574.25,1945.48) ; C20.2@840,1885 844.25,1880.75 v1(844.25,1855.48) 844.25,1825.75 R29.1@845,1825
  Bottom Layer w8: R178.1@337,2101.62 337,2102.53 360,2125.53 J3.2@360,2245 ; R183.2@520,1975 529.08,1984.08 v1(564.08,1984.08)
  other v1: 735,2245 730,2337.11 730,2365
S_4S: C58.2 C61.1 C71.2 D20.2 J7.2 J7.3 J7.4 J7.5 J14.068 J14.069 R122.1 R296.2 R315.1 R321.2 U19.3 | length 300.9
  Top Layer w8: D20.2@545,-1052.91 546.61,-1054.52 v1(574.25,-1054.52) ; R122.1@843.62,-1179 840,-1175.38 v1(840,-1145) 840,-1114.58 C71.2@843.58,-1111
  Bottom Layer w8: R315.1@337,-898.38 337,-897.47 360,-874.47 J7.2@360,-755 ; R321.2@520,-1025 525,-1020 v1(565,-1020)
  other v1: 685.33,-800.24 723.32,-674.5
T_AMB: R97.1 U9.21 U17.1 | length 393.2
  Top Layer w8: U9.21@-2963.58,-677.17 -2844.36,-677.17 -2829.53,-692 R97.1@-2828.62,-692 -2827.72,-692 -2797.76,-662.04 -2730.98,-662.04 -2702,-633.06 -2702,-601.38 -2673.99,-573.38 -2658.01,-573.38 U17.1@-2648.23,-563.6
TEMP_P: C189.1 R89.1 U9.39 | length 218.2
  Top Layer w8: U9.39@-2963.58,-393.7 -2893.84,-393.7 -2885.14,-385 v1(-2880,-385) -2876.36,-388.64 -2860.89,-388.64 -2829.53,-420 R89.1@-2828.62,-420
  Bottom Layer w8: v1(-2880,-385) -2861.86,-366.86 -2843.44,-366.86 C189.1@-2828.58,-352
TEMP_S: C191.1 R91.1 U9.17 | length 488.1
  Top Layer w8: U9.17@-2963.58,-740.16 -2957.99,-745.75 -2914.39,-745.75 v1(-2910.76,-749.39) ; v1(-2870,-480) -2866.54,-480 -2856.54,-490 -2830.62,-490 R91.1@-2828.62,-488
  Bottom Layer w8: v1(-2910.76,-749.39) -2884.5,-723.13 -2884.5,-670.5 -2910,-645 -2910,-593.94 -2870,-553.94 v1(-2870,-480) -2866.36,-476.36 -2866.36,-456.88 -2829.48,-420 C191.1@-2828.53,-420
VDC_P: C201.1 R100.2 U9.11 | length 411.5
  Top Layer w8: U9.11@-2963.58,-834.65 -2963.41,-834.82 -2910.18,-834.82 v1(-2910,-835) -2908.94,-835 -2890.81,-816.88 -2886.4,-816.88 -2829.53,-760 R100.2@-2828.62,-760
  Bottom Layer w8: v1(-2910,-835) -2875,-800 -2875,-755 -2865,-745 -2865,-659.47 -2829.53,-624 C201.1@-2828.58,-624
VDC_S: C209.1 R107.2 U9.9 | length 305.3
  Top Layer w8: U9.9@-2963.58,-866.14 -2911.48,-866.14 v1(-2894.48,-883.14) -2877.48,-900.14 -2832.76,-900.14 R107.2@-2828.62,-896
  Bottom Layer w8: v1@-2891.98,-885.65 v1(-2894.48,-883.14) -2894.48,-855.55 -2884.5,-845.56 -2884.5,-845.19 -2859.48,-820.18 -2859.48,-805.07 -2859,-804.59 -2859,-789.47 -2829.53,-760 C209.1@-2828.58,-760
VIN: J11.1 Q1.5 R7.2 R8.2 U1.1 | length 183.7
  Top Layer w8: R7.2@-3605,3400.47 -3605,3389.47 -3584.16,3368.64 -3578.64,3368.64 v1(-3575,3365) ; v1@-3575,3368.82 -3569.65,3368.82 -3537.09,3401.38 R8.2@-3535,3401.38 ; v1(-3410,3710) -3433.73,3710 -3435.63,3711.91 U1.1@-3435.63,3722.09 -3435.63,3738.09 -3433.73,3740 v1(-3410,3740)
VIN_MID: Q1.1 Q1.2 Q1.3 Q2.1 Q2.2 Q2.3
VIN_PROTECT: Q2.5 R13.1 U1.9 | length 443.3
  Top Layer w8: v1(-3465,3495) -3461.36,3498.64 -3461.36,3510.62 -3457.1,3514.89 -3457.1,3546.13 U1.9@-3455.31,3547.91 U1.9@-3453.54,3549.69
  Bottom Layer w8: v1(-3786.73,3345) -3705.87,3345 -3555.87,3495 v1(-3465,3495)
VP_N: C40.2 R67.2 R95.2 | length 1411.6
  Top Layer w8: R95.2@-2371.38,-624 -2370.47,-624 -2345.47,-649 -2147.01,-649 -2008.64,-510.63 -2008.64,-498.64 v1(-2005,-495) ; v1(-1430,110) -1426.36,113.64 -1411.89,113.64 -1389.53,136 C40.2@-1388.58,136 R67.2@-1388.62,204 R67.2@-1388.62,204
  Bottom Layer w8: v1(-2005,-495) -1719.05,-209.05 -1719.05,-177.99 -1431.06,110 v1(-1430,110)
VP_P: C40.1 R70.2 R98.2 | length 1416.6
  Top Layer w8: R98.2@-2371.38,-692 -2344.38,-665 -2135,-665 v1(-1970,-500) ; v1(-1430,75) -1395.62,75 R70.2@-1388.62,68 -1387.72,68 -1347.24,108.48 -1347.24,121.14 -1332.37,136 C40.1@-1331.42,136
  Bottom Layer w8: v1(-1970,-500) -1700,-230 -1700,-195 v1(-1430,75)
VS_N: C51.2 R82.2 R102.2 | length 8699.7
  Top Layer w8: R102.2@-2371.38,-828 -2344.38,-855 -1977.37,-855 -1760,-1072.37 -1760,-2567.37 -1193.37,-3134 1178.37,-3134 1516.75,-2795.63 1516.75,-2475.63 1609,-2383.37 1609,-1817.69 1579,-1787.69 1579,-349 1434,-204 R82.2@1388.62,-204 1387.72,-204 1347.24,-163.52 1347.24,-150.86 1332.37,-136 C51.2@1331.42,-136
VS_P: C51.1 R78.2 R108.2 | length 8746.5
  Top Layer w8: R108.2@-2371.38,-896 -2370.47,-896 -2356.52,-882.04 -2356.52,-881.14 -2350.38,-875 -1980,-875 -1776,-1079 -1776,-2574 -1200,-3150 1185,-3150 1535,-2800 1535,-2480 1625,-2390 1625,-1811.06 1595,-1781.06 1595,-341.47 1389.53,-136 C51.1@1388.58,-136 R78.2@1388.62,-68 R78.2@1388.62,-68
pads on no net: J12.1 J12.4 J12.6 J12.8 MH1.1 MH3.1 MH4.1 MH5.1 MH6.1 MH7.1 MH8.1 U3.16 U4.16 U7.3 U7.11 U8.3 U8.11 U9. U9.1 U9.2 U9.3 U9.4 U9.5 U9.6 U9.8 U9.15 U9.18 U9.23 U9.24 U9.25 U9.26 U9.27 U9.30 U9.32 U9.33 U9.34 U9.36 U9.37 U9.41 U9.42 U9.43 U9.44 U9.45 U9.58 U9.60 U9.61 U9.63 U9.66 U9.68 U9.69 U9.70 U9.71 U9.73 U9.75 U9.82 U9.85 U9.86 U9.89 U9.90 U9.93 U9.100 U9.102 U9.104 U9.105 U9.106 U9.108 U9.110 U9.113 U9.114 U9.115 U9.116 U9.117 U9.118 U9.119 U9.MH1 U9.MH2 U11.16 U12.11 U12.12 U12.13 U12.14 U12.15 U12.16 U13.6 U13.9 U18.16 U19.16 U22.3 U22.11 U23.3 U23.11 U25.16 U26.4 U27.4 U32.1 U33.4 U34.4 U35.6 U35.9 U35.10 U35.11 U36.6 U36.9 U37.1 U38.4 U39.4 U40.1 U41.1 U46.4 U47.4

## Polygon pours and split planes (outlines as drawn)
GH_3P on Top Layer "GH_3P_L01_P005" (solid, pour order 5): -630,1955 -435,1955 -435,2070 -705,2070 -780,2145 -870,2145 -870,2110 -785,2110
S_4P on Top Layer "NONET_L02_P-001" (solid, pour order 929): 610,2205 865,2205 865,2255 805,2255 750,2310 750,2375 680,2375 680,2290 610,2290
GH_4P on Top Layer "GH_4P_L01_P025" (solid, pour order 25): 540,2080 665,2080 695,2110 695,2155 865,2155 865,2195 645,2195 645,2140 580,2140 505,2140 505,2190 445,2190 445,2080
CLMP_4P on Top Layer "CLMP_4P_L01_P037" (solid, pour order 37): 585,2155 635,2155 635,2165 670,2165 670,2195 585,2195
S_2P on Top Layer "NONET_L02_P-001" (solid, pour order 935): -725,650 -725,580 -645,580 -645,620 -680,620 -680,705 -610,705 -610,800 -695,800 -695,785 -870,785 -870,750 -825.17,750 -725.17,650
CLMP_2P on Top Layer "CLMP_2P_L01_P187" (solid, pour order 187): -585,845 -635,845 -635,835 -670,835 -670,805 -585,805
GH_2P on Top Layer "GH_2P_L01_P181" (solid, pour order 181): -540,920 -665,920 -695,890 -695,845 -865,845 -865,805 -645,805 -645,860 -580,860 -505,860 -505,810 -445,810 -445,920
S_2S on Top Layer "S_2S_L01_P307" (solid, pour order 307): -807.23,-2257.77 -760,-2305 -730.11,-2334.89 -680,-2335.07 -680,-2290 -570,-2290 -570,-2205 -670,-2205 -670,-2190 -700,-2190 -700,-2210 -865,-2210 -865,-2257.77
S_4S on Top Layer "S_4S_L01_P272" (solid, pour order 272): 670,-795 670,-810 700,-810 700,-790 865,-790 865,-745 810,-745 730.11,-665.11 680,-664.93 680,-710 570,-710 570,-795
GH_4S on Top Layer "GH_4S_L01_P268" (solid, pour order 268): 540,-920 665,-920 695,-890 695,-845 865,-845 865,-805 645,-805 645,-860 580,-860 505,-860 505,-810 445,-810 445,-920
S_3S on Top Layer "NONET_L02_P-001" (solid, pour order 934): -870,-900 -870,-955 -785,-955 -751.84,-988.16 -751.84,-1083.34 -696.66,-1083.34 -695,-1085 -695,-990 -785,-900
G_3S on Top Layer "Top Layer-G_3S" (solid, pour order 395): -425,-1045 -170,-1045 -135,-1080 -9.88,-1080 ccw(c-10,-1055) 15,-1055.12 15,-949.88 ccw(c-10,-950) -9.88,-925 -200,-925 -320,-805 -350,-775 -580,-775 -580,-845 -500,-845 -500,-800 -425,-800
GH_3S on Top Layer "GH_3S_L01_P254" (solid, pour order 254): -630,-1045 -435,-1045 -435,-930 -705,-930 -780,-855 -870,-855 -870,-890 -785,-890
S_1S on Top Layer "NONET_L02_P-001" (solid, pour order 931): 700,-1915 700,-2010 785,-2095 870,-2095 870,-2045 785,-2045 755,-2015 755,-1915
G_1S on Top Layer "Top Layer-G_1S" (solid, pour order 459): 18 vertices, not listed, extent 0,-2230 575,-1605
GH_1S on Top Layer "GH_1S_L01_P279" (solid, pour order 279): 630,-1955 435,-1955 435,-2070 705,-2070 780,-2145 870,-2145 870,-2110 785,-2110
GH_1P on Top Layer "GH_1P_L01_P096" (solid, pour order 96): 630,1045 435,1045 435,930 705,930 780,855 870,855 870,890 785,890
G_1P on Top Layer "Top Layer-G_1P" (solid, pour order 129): 20 vertices, not listed, extent -15,780 580,1200
S_1P on Top Layer "NONET_L02_P-001" (solid, pour order 930): 700,1085 700,990 785,905 870,905 870,955 785,955 755,985 755,1085
-4V_2P on Top Layer "-4V_2P_L01_P184" (solid, pour order 184): -705,990 -705,1070 -820,1070 -865,1070 -865,1000 -770,1000 -770,990
G_2P on Top Layer "Top Layer-G_2P" (solid, pour order 225): 17 vertices, not listed, extent -580,625 -5,1040
S_3P on Top Layer "NONET_L02_P-001" (solid, pour order 926): -870,2090 -870,2045 -780,2045 -750,2015 -750,1930 -710,1930 -710,2025 -775,2090
G_3P on Top Layer "Top Layer-G_4P" (solid, pour order 66): -225,1955 -75,1805 80,1805 80,1850 35,1895 -290,2220 -325,2220 -580,2220 -580,2155 -495,2155 -495,2200 -425,2200 -425,1955 -325,1955
GL_2P on Top Layer "GL_2P_L01_P182" (solid, pour order 182): -530,930 -675,930 -695,910 -865,910 -865,945 -710,945 -655,1000 -560,1000 -520,1040 -445,1040 -445,930
G_2S on Top Layer "Top Layer-G_2S" (solid, pour order 365): -575,-2225 -330,-2225 -330,-2200 -25,-2200 -25,-2025 -240,-2025 -310,-1955 -430,-1955 -430,-2200 -515,-2200 -515,-2150 -575,-2150
GL_2S on Top Layer "GL_2S_L01_P304" (solid, pour order 304): -530,-2070 -675,-2070 -695,-2090 -865,-2090 -865,-2055 -710,-2055 -655,-2000 -560,-2000 -520,-1960 -445,-1960 -445,-2070
G_4S on Top Layer "Top Layer-G_4S" (solid, pour order 390): 15,-755 305,-1045 435,-1045 435,-800 515,-800 515,-845 575,-845 575,-780 380,-780 245,-780 190,-725 190,-644.88 ccw(c165,-645) 165.12,-620 39.88,-620 ccw(c40,-645) 15,-644.88
GL_4S on Top Layer "GL_4S_L01_P269" (solid, pour order 269): 530,-930 675,-930 695,-910 865,-910 865,-945 710,-945 655,-1000 560,-1000 520,-1040 445,-1040 445,-930
G_4P on Top Layer "Top Layer-G_4P 1" (solid, pour order 405): 385,2195 510,2195 510,2150 580,2150 580,2220 390,2220 375,2235 -50.12,2235 ccw(c-50,2210) -75,2210.12 -75,2149.88 ccw(c-50,2150) -50.12,2125 85,2125 250,1960 385,1960
GL_4P on Top Layer "GL_4P_L01_P026" (solid, pour order 26): 530,2070 675,2070 695,2090 865,2090 865,2055 710,2055 655,2000 560,2000 520,1960 445,1960 445,2070
GND on Top Layer "Top Layer-GND" (solid, pour order 919): -1560.12,3560 -1460,3560 -1460,3900 -1560.12,3900 ccw(c-1560,3875) -1585,3875.12 -1585,3584.88 ccw(c-1560,3585)
VIN_MID on Top Layer "Top Layer-VIN_MID" (solid, pour order 850): -3664.88,3370 ccw(c-3665,3395) -3640,3394.88 -3640,3815.12 ccw(c-3665,3815) -3664.88,3840 -3735.12,3840 ccw(c-3735,3815) -3760,3815.12 -3760,3394.88 ccw(c-3735,3395) -3735.12,3370
+12V on Top Layer "Top Layer-+12V" (solid, pour order 843): -3674.88,2960 ccw(c-3675,2985) -3650,2984.88 -3650,3110.12 ccw(c-3675,3110) -3674.88,3135 -3980.12,3135 ccw(c-3980,3110) -4005,3110.1 -4005,2984.9 ccw(c-3980,2985) -3980.12,2960
VIN_PROTECT on Top Layer "Top Layer-VIN_PROTECT" (solid, pour order 568): -3990,3224.88 ccw(c-3965,3225) -3965.12,3200 -3794.88,3200 ccw(c-3795,3225) -3770,3224.88 -3770,3585.12 ccw(c-3795,3585) -3794.88,3610 -3965.12,3610 ccw(c-3965,3585) -3990,3585.12
VIN on Top Layer "Top Layer-VIN" (solid, pour order 565): -3980.12,3625 -3794.88,3625 ccw(c-3795,3650) -3770,3649.88 -3770,3875.12 ccw(c-3795,3875) -3794.88,3900 -4295.12,3900 ccw(c-4295,3875) -4320,3875.12 -4320,3224.88 ccw(c-4295,3225) -4295.12,3200 -4029.88,3200 ccw(c-4030,3225) -4005,3224.88 -4005,3600.12 cw(c-3980,3600)
NetMH2_1 on Top Layer "NONET_L02_P-001" (solid, pour order 487): -1395,3900 -1395,3560 -1010,3560 -1010,3900
DCDCO_S on Top Layer "NONET_L02_P-001" (solid, pour order 435): 850,145 850,225 645,225 645,95 695,95 695,60 850,60 850,105 740,105 740,145
-4V_2S on Top Layer "-4V_2S_L01_P306" (solid, pour order 306): -705,-2010 -705,-1930 -820,-1930 -820,-1800 -865,-1800 -865,-2000 -770,-2000 -770,-2010
-4V_4P on Top Layer "-4V_4P_L01_P029" (solid, pour order 29): 705,2010 705,1930 820,1930 820,1800 865,1800 865,2000 770,2000 770,2010
GND on Top Layer "NONET_L02_P-001" (solid, pour order 362): 1270,-1125 1270,-995 1135,-995 1135,-1125
GND on Top Layer "NONET_L02_P-001" (solid, pour order 358): 1270,-2425 1270,-2295 1135,-2295 1135,-2425
GND on Top Layer "NONET_L02_P-001" (solid, pour order 354): -1270,-1875 -1270,-2005 -1135,-2005 -1135,-1875
GND on Top Layer "NONET_L02_P-001" (solid, pour order 350): -1270,-575 -1270,-705 -1135,-705 -1135,-575
GND on Top Layer "NONET_L-01_P-001" (solid, pour order 346): -1270,-575 -1270,-705 -1130,-705 -1130,-575
+15V_2S on Top Layer "+15V_2S_L01_P312" (solid, pour order 312): -570,-2375 -570,-2305 -670,-2305 -670,-2375
S_2S on Top Layer "S_2S_L01_P311" (solid, pour order 311): -425,-2375 -425,-2325 -510,-2325 -510,-2305 -555,-2305 -555,-2375
CLMP_2S on Top Layer "CLMP_2S_L01_P310" (solid, pour order 310): -640,-2000 -640,-1965 -700,-1965 -700,-2015 -865,-2015 -865,-2050 -710,-2050 -660,-2000
CLMP_2S on Top Layer "CLMP_2S_L01_P309" (solid, pour order 309): -585,-2155 -635,-2155 -635,-2165 -670,-2165 -670,-2195 -585,-2195
-4V_2S on Top Layer "-4V_2S_L01_P308" (solid, pour order 308): -455,-2315 -455,-2225 -555,-2225 -555,-2315
+15V_2S on Top Layer "+15V_2S_L01_P305" (solid, pour order 305): -705,-2150 -705,-2095 -865,-2095 -865,-2150
GH_2S on Top Layer "GH_2S_L01_P303" (solid, pour order 303): -540,-2080 -665,-2080 -695,-2110 -695,-2155 -865,-2155 -865,-2195 -645,-2195 -645,-2140 -580,-2140 -505,-2140 -505,-2190 -445,-2190 -445,-2080
-4V_1S on Top Layer "Top Layer--4V_4P" (solid, pour order 285): 600,-2225 510,-2225 510,-2295 570,-2295 570,-2380 845.12,-2380 ccw(c845,-2355) 870,-2355.12 870,-2305 600,-2305
+15V_1S on Top Layer "+15V_1S_L01_P284" (solid, pour order 284): 610,-2295 610,-2220 690,-2220 690,-2295
S_1S on Top Layer "S_1S_L01_P283" (solid, pour order 283): 560,-2380 560,-2305 440,-2305 440,-2380
CLMP_1S on Top Layer "CLMP_1S_L01_P282" (solid, pour order 282): 770,-2255 670,-2155 595,-2155 595,-2205 670,-2205 760,-2295 870,-2295 870,-2255
GL_1S on Top Layer "GL_1S_L01_P281" (solid, pour order 281): 675,-2145 480,-2145 480,-2190 435,-2190 435,-2080 645,-2080 770,-2205 870,-2205 870,-2245 775,-2245
+15V_1S on Top Layer "+15V_1S_L01_P280" (solid, pour order 280): 870,-2195 870,-2155 775,-2155 725,-2105 705,-2125 775,-2195
+15V_4S on Top Layer "+15V_4S_L01_P277" (solid, pour order 277): 570,-625 570,-695 670,-695 670,-625
S_4S on Top Layer "S_4S_L01_P276" (solid, pour order 276): 425,-625 425,-675 510,-675 510,-695 555,-695 555,-625
CLMP_4S on Top Layer "CLMP_4S_L01_P275" (solid, pour order 275): 640,-1000 640,-1035 700,-1035 700,-985 865,-985 865,-950 710,-950 660,-1000
CLMP_4S on Top Layer "CLMP_4S_L01_P274" (solid, pour order 274): 585,-845 635,-845 635,-835 670,-835 670,-805 585,-805
-4V_4S on Top Layer "-4V_4S_L01_P273" (solid, pour order 273): 455,-685 455,-775 555,-775 555,-685
-4V_4S on Top Layer "-4V_4S_L01_P271" (solid, pour order 271): 705,-990 705,-1070 820,-1070 820,-1200 865,-1200 865,-1000 770,-1000 770,-990
+15V_4S on Top Layer "+15V_4S_L01_P270" (solid, pour order 270): 705,-850 705,-905 865,-905 865,-850
-4V_3S on Top Layer "Top Layer--4V_4P" (solid, pour order 260): -600,-775 -510,-775 -510,-705 -570,-705 -570,-620 -845.12,-620 ccw(c-845,-645) -870,-644.88 -870,-695 -600,-695
+15V_3S on Top Layer "+15V_3S_L01_P259" (solid, pour order 259): -610,-705 -610,-780 -690,-780 -690,-705
S_3S on Top Layer "S_3S_L01_P258" (solid, pour order 258): -560,-620 -560,-695 -440,-695 -440,-620
CLMP_3S on Top Layer "CLMP_3S_L01_P257" (solid, pour order 257): -770,-745 -670,-845 -595,-845 -595,-795 -670,-795 -760,-705 -870,-705 -870,-745
GL_3S on Top Layer "GL_3S_L01_P256" (solid, pour order 256): -675,-855 -480,-855 -480,-810 -435,-810 -435,-920 -645,-920 -770,-795 -870,-795 -870,-755 -775,-755
+15V_3S on Top Layer "+15V_3S_L01_P255" (solid, pour order 255): -870,-805 -870,-845 -775,-845 -725,-895 -705,-875 -775,-805
DCDCO_P on Top Layer "NONET_L02_P-001" (solid, pour order 252): -850,-145 -850,-225 -645,-225 -645,-95 -695,-95 -695,-60 -850,-60 -850,-105 -740,-105 -740,-145
HLDOO_P on Top Layer "NONET_L02_P-001" (solid, pour order 251): -850,40 -850,-5 -765,-5 -765,-45 -725,-45 -725,40
+5V on Top Layer "NONET_L02_P-001" (solid, pour order 249): 1150,-40 1355,-40 1355,95 1290,95 1270,75 1270,0 1150,0
+5V on Top Layer "NONET_L02_P-001" (solid, pour order 248): -1150,40 -1355,40 -1355,-95 -1290,-95 -1270,-75 -1270,0 -1150,0
GND on Top Layer "NONET_L-01_P-001" (solid, pour order 147): -1270,2425 -1270,2295 -1130,2295 -1130,2425
GND on Top Layer "NONET_L02_P-001" (solid, pour order 235): -1270,2425 -1270,2295 -1135,2295 -1135,2425
GND on Top Layer "NONET_L02_P-001" (solid, pour order 239): 1270,575 1270,705 1135,705 1135,575
GND on Top Layer "NONET_L02_P-001" (solid, pour order 243): -1270,1125 -1270,995 -1135,995 -1135,1125
GND on Top Layer "NONET_L02_P-001" (solid, pour order 247): 1270,1875 1270,2005 1135,2005 1135,1875
+15V_2P on Top Layer "+15V_2P_L01_P190" (solid, pour order 190): -570,625 -570,695 -670,695 -670,625
S_2P on Top Layer "S_2P_L01_P189" (solid, pour order 189): -425,625 -425,675 -510,675 -510,695 -555,695 -555,625
CLMP_2P on Top Layer "CLMP_2P_L01_P188" (solid, pour order 188): -640,1000 -640,1035 -700,1035 -700,985 -865,985 -865,950 -710,950 -660,1000
-4V_2P on Top Layer "-4V_2P_L01_P186" (solid, pour order 186): -455,685 -455,775 -555,775 -555,685
+15V_2P on Top Layer "+15V_2P_L01_P183" (solid, pour order 183): -705,850 -705,905 -865,905 -865,850
+15V_1P on Top Layer "+15V_1P_L01_P101" (solid, pour order 101): 610,705 610,780 690,780 690,705
-4V_1P on Top Layer "Top Layer--4V_4P" (solid, pour order 102): 600,775 510,775 510,705 570,705 570,620 845.12,620 ccw(c845,645) 870,644.88 870,695 600,695
S_1P on Top Layer "S_1P_L01_P100" (solid, pour order 100): 560,620 560,695 440,695 440,620
CLMP_1P on Top Layer "CLMP_1P_L01_P099" (solid, pour order 99): 770,745 670,845 595,845 595,795 670,795 760,705 870,705 870,745
GL_1P on Top Layer "GL_1P_L01_P098" (solid, pour order 98): 675,855 480,855 480,810 435,810 435,920 645,920 770,795 870,795 870,755 775,755
+15V_1P on Top Layer "+15V_1P_L01_P097" (solid, pour order 97): 870,805 870,845 775,845 725,895 705,875 775,805
-4V_3P on Top Layer "Top Layer--4V_4P" (solid, pour order 63): -600,2225 -510,2225 -510,2295 -570,2295 -570,2380 -845.12,2380 ccw(c-845,2355) -870,2355.12 -870,2305 -600,2305
+15V_4P on Top Layer "+15V_4P_L01_P045" (solid, pour order 45): 570,2375 570,2305 670,2305 670,2375
S_4P on Top Layer "S_4P_L01_P042" (solid, pour order 42): 425,2375 425,2325 510,2325 510,2305 555,2305 555,2375
CLMP_4P on Top Layer "CLMP_4P_L01_P038" (solid, pour order 38): 640,2000 640,1965 700,1965 700,2015 865,2015 865,2050 710,2050 660,2000
-4V_4P on Top Layer "-4V_4P_L01_P035" (solid, pour order 35): 455,2315 455,2225 555,2225 555,2315
+15V_4P on Top Layer "+15V_4P_L01_P028" (solid, pour order 28): 705,2150 705,2095 865,2095 865,2150
+15V_3P on Top Layer "+15V_3P_L01_P024" (solid, pour order 24): -610,2295 -610,2220 -690,2220 -690,2295
CLMP_3P on Top Layer "CLMP_3P_L01_P011" (solid, pour order 11): -770,2255 -670,2155 -595,2155 -595,2205 -670,2205 -760,2295 -870,2295 -870,2255
GL_3P on Top Layer "GL_3P_L01_P007" (solid, pour order 7): -675,2145 -480,2145 -480,2190 -435,2190 -435,2080 -645,2080 -770,2205 -870,2205 -870,2245 -775,2245
S_3P on Top Layer "S_3P_L01_P019" (solid, pour order 19): -560,2380 -560,2305 -440,2305 -440,2380
+15V_3P on Top Layer "+15V_3P_L01_P006" (solid, pour order 6): -870,2195 -870,2155 -775,2155 -725,2105 -705,2125 -775,2195
GND on Bottom Layer "NONET_L-01_P-001" (solid, pour order 237): 1270,575 1270,850 1235,850 1235,895 1160,895 1160,575
-4V_3P on Bottom Layer "NONET_L02_P-001" (solid, pour order 925): -840,1970 -840,1850 -740,1850 -705,1885 -705,1910 -765,1910 -765,1970
-4V_1S on Bottom Layer "-4V_1S_L06_P933" (solid, pour order 933): 750,-1840 705,-1885 705,-1910 760,-1910 760,-1970 840,-1970 840,-1840
RLIM_4P on Bottom Layer "RLIM_4P_L06_P031" (solid, pour order 31): 840,2280 840,2255 765,2255 735,2225 590,2225 590,2265 605,2280
+15V_4P on Bottom Layer "+15V_4P_L06_P027" (solid, pour order 27): 845,2200 845,2155 760,2155 760,2090 705,2090 705,2200
CLMP_4P on Bottom Layer "CLMP_4P_L06_P039" (solid, pour order 39): 650,2195 650,2160 650,1970 680,1970 680,2195
-4V_1P on Bottom Layer "-4V_1P_L06_P107" (solid, pour order 107): 750,1160 705,1115 705,1090 760,1090 760,1030 840,1030 840,1160
S_2P on Bottom Layer "Bottom Layer-S_2P" (solid, pour order 204): -675,525 -635,525 -635,585 -605,615 -605,635 -605,695 -735,695 -735,660 -710,660 -710,585 -675,585
RLIM_2P on Bottom Layer "RLIM_2P_L06_P192" (solid, pour order 192): -840,725 -840,745 -770,745 -740,775 -590,775 -590,735 -600,725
